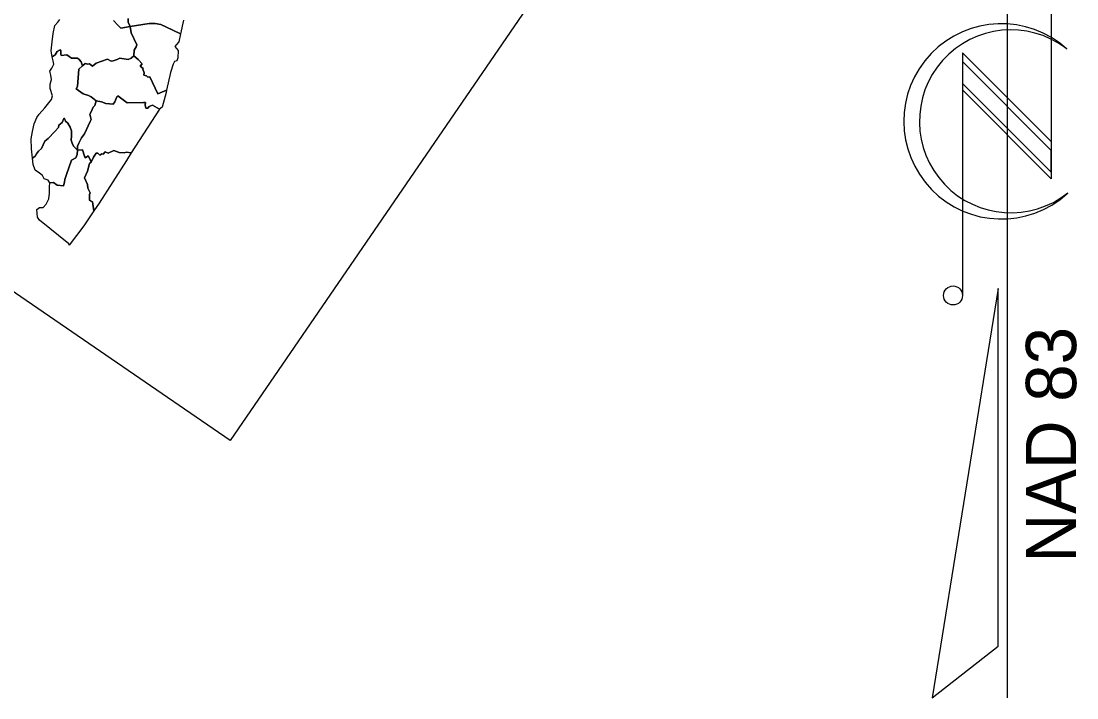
# Model space of a CAD drawing. Extents: x 1638787 to 1643250, y 391480 to 396306.
# Drawn here: x 1641235.6 to 1641581.8, y 395313.5 to 395535.3 of the extents above; entities that cross this region are included whole.
import ezdxf

# ---------------------------------------------------------------- set-up
doc = ezdxf.new("R2010")
doc.units = 0
doc.layers.add('Old_Level_5', color=7, linetype='Continuous')
doc.layers.add('Sheet North Arrow CELL', color=7, linetype='Continuous')

msp = doc.modelspace()

# ---------------------------------------------------------------- linework, layer by layer
at = {"layer": 'Old_Level_5'}
msp.add_lwpolyline([(1641120.36, 395523.82), (1641374.86, 395894.94), (1641558.57, 395768.96), (1641304.08, 395397.83)], close=True, dxfattribs=at)
for points in [[(1641265.88, 395535.48), (1641267.23, 395534), (1641268.21, 395533.04), (1641271.28, 395533.59), (1641271.64, 395531.49), (1641273.51, 395527.54), (1641273.33, 395526.86), (1641272.59, 395525.75), (1641272.47, 395523.92), (1641271.66, 395523.13), (1641270.68, 395522.75), (1641267.92, 395523.18), (1641267.05, 395522.76), (1641265.77, 395522.24), (1641265.05, 395522.2), (1641263.91, 395522.88), (1641260.14, 395521.52), (1641258.92, 395520.5), (1641257.99, 395521.32), (1641257.46, 395521.19), (1641256.57, 395521.4), (1641255.68, 395520.68), (1641255.25, 395521.98), (1641254.63, 395522.69), (1641254.04, 395523.15), (1641252.08, 395523.19), (1641250.53, 395524.23), (1641248.72, 395524.07), (1641248.59, 395524.6), (1641248.6, 395525.61), (1641248.41, 395525.87), (1641247.36, 395525.35), (1641246.76, 395524.29), (1641245.73, 395523.6), (1641245.36, 395525.52), (1641245.69, 395528.53), (1641246.08, 395531.23), (1641246.6, 395533.82), (1641247.65, 395534.99), (1641248.27, 395535.88)], [(1641270.62, 395536.21), (1641270.71, 395535.02), (1641271.28, 395533.59), (1641268.21, 395533.04), (1641267.23, 395534), (1641265.88, 395535.48)], [(1641288.82, 395535.57), (1641287.8, 395531.09), (1641283.06, 395533.41), (1641281.34, 395534.19), (1641279.48, 395534.52), (1641277.59, 395534.52), (1641271.28, 395533.59), (1641270.71, 395535.02), (1641270.62, 395536.21)], [(1641271.28, 395533.59), (1641277.59, 395534.52), (1641279.48, 395534.52), (1641281.34, 395534.19), (1641283.06, 395533.41), (1641287.8, 395531.09), (1641287.26, 395528.55), (1641286.55, 395527.65), (1641285.93, 395526.95), (1641286.48, 395526.37), (1641287.04, 395525.71), (1641286.9, 395523.23), (1641286.68, 395522.32), (1641285.81, 395522.08), (1641285.37, 395521.22), (1641284.5, 395518.47), (1641283.27, 395512.7), (1641280.38, 395511.49), (1641277.8, 395517.06), (1641277.14, 395516.97), (1641276.64, 395517.35), (1641275.84, 395517.64), (1641275.91, 395518.39), (1641275.43, 395519.52), (1641275.54, 395519.83), (1641274.62, 395520.57), (1641275.25, 395521.27), (1641273.89, 395522.74), (1641272.47, 395523.92), (1641272.59, 395525.75), (1641273.33, 395526.86), (1641273.51, 395527.54), (1641271.64, 395531.49), (1641271.28, 395533.59)], [(1641249.56, 395503.38), (1641249.06, 395502.05), (1641247.88, 395501.17), (1641247.79, 395500.41), (1641246.63, 395499.17), (1641244.48, 395496.79), (1641243.38, 395495.91), (1641242.19, 395493.52), (1641241.23, 395492.69), (1641240.58, 395491.75), (1641240.21, 395491.06), (1641239.33, 395490.41), (1641239.01, 395493.44), (1641238.87, 395496.67), (1641239.24, 395499.11), (1641239.86, 395501.59), (1641240.66, 395503.66), (1641241.52, 395504.84), (1641243.34, 395506.92), (1641245.57, 395509.66), (1641245.82, 395510.87), (1641245.12, 395513.27), (1641245.08, 395514.65), (1641245.52, 395516.19), (1641245.27, 395517.6), (1641245.01, 395518.92), (1641245.58, 395519.93), (1641246.26, 395521.19), (1641246.07, 395522.29), (1641245.73, 395523.6), (1641246.76, 395524.29), (1641247.36, 395525.35), (1641248.41, 395525.87), (1641248.6, 395525.61), (1641248.59, 395524.6), (1641248.72, 395524.07), (1641250.53, 395524.23), (1641252.08, 395523.19), (1641254.04, 395523.15), (1641254.63, 395522.69), (1641255.25, 395521.98), (1641255.68, 395520.68), (1641254.53, 395519.58), (1641254.01, 395513.9), (1641253.56, 395513.11), (1641255.87, 395511.49), (1641257.63, 395510.96), (1641258.57, 395510.53), (1641260.19, 395509.18), (1641259.7, 395507.69), (1641259.15, 395507.08), (1641258.54, 395505.53), (1641258.08, 395504.83), (1641258.55, 395503.09), (1641258.15, 395502.35), (1641256.35, 395498.41), (1641255.31, 395497.05), (1641254.54, 395495.31), (1641254.03, 395494.35), (1641254.07, 395492.98), (1641252.81, 395494.17), (1641252.44, 395494.98), (1641252.02, 395496.28), (1641252.06, 395497.74), (1641252.09, 395499.39), (1641251.68, 395500.51), (1641250.89, 395501.87), (1641250.15, 395502.52), (1641249.74, 395503.38), (1641249.56, 395503.38)], [(1641254.53, 395519.58), (1641255.68, 395520.68), (1641256.57, 395521.4), (1641257.46, 395521.19), (1641257.99, 395521.32), (1641258.92, 395520.5), (1641260.14, 395521.52), (1641263.91, 395522.88), (1641265.05, 395522.2), (1641265.77, 395522.24), (1641267.05, 395522.76), (1641267.92, 395523.18), (1641270.68, 395522.75), (1641271.66, 395523.13), (1641272.47, 395523.92), (1641273.89, 395522.74), (1641275.25, 395521.27), (1641274.62, 395520.57), (1641275.54, 395519.83), (1641275.43, 395519.52), (1641275.91, 395518.39), (1641275.84, 395517.64), (1641276.64, 395517.35), (1641277.14, 395516.97), (1641277.8, 395517.06), (1641280.38, 395511.49), (1641283.27, 395512.7), (1641283.17, 395511.94), (1641281.79, 395507.12), (1641280.99, 395506.41), (1641278.64, 395507.76), (1641277.57, 395507.29), (1641277.11, 395506.77), (1641276.49, 395506.81), (1641276.21, 395507.9), (1641276.31, 395508.66), (1641275.64, 395508.66), (1641270.37, 395508.48), (1641267.3, 395510.79), (1641266.92, 395510.45), (1641266.31, 395508.81), (1641265.72, 395508.07), (1641263.33, 395508.34), (1641261.93, 395508.9), (1641260.19, 395509.18), (1641258.57, 395510.53), (1641257.63, 395510.96), (1641255.87, 395511.49), (1641253.56, 395513.11), (1641254.01, 395513.9), (1641254.53, 395519.58)], [(1641286.9, 395523.23), (1641286.68, 395522.32), (1641285.81, 395522.08), (1641285.37, 395521.22), (1641284.5, 395518.47), (1641283.27, 395512.7), (1641283.17, 395511.94)], [(1641259.7, 395507.69), (1641260.19, 395509.18), (1641261.93, 395508.9), (1641263.33, 395508.34), (1641265.72, 395508.07), (1641266.31, 395508.81), (1641266.92, 395510.45), (1641267.3, 395510.79), (1641270.37, 395508.48), (1641275.64, 395508.66), (1641276.31, 395508.66), (1641276.21, 395507.9), (1641276.49, 395506.81), (1641277.11, 395506.77), (1641277.57, 395507.29), (1641278.64, 395507.76), (1641280.99, 395506.41), (1641271.68, 395492.17), (1641269.96, 395492.36), (1641269.49, 395492.1), (1641267.72, 395492.26), (1641265.96, 395492.88), (1641264.07, 395492.03), (1641263.17, 395492.41), (1641262.51, 395491.74), (1641261.98, 395491.79), (1641261.35, 395491.35), (1641260.69, 395492), (1641260.16, 395492.05), (1641259.28, 395490.66), (1641258.57, 395489.02), (1641258.06, 395490.13), (1641257.52, 395491.1), (1641256.98, 395490.67), (1641256.63, 395490.54), (1641256.38, 395491.03), (1641255.64, 395493.1), (1641254.07, 395492.98), (1641254.03, 395494.35), (1641254.54, 395495.31), (1641255.31, 395497.05), (1641256.35, 395498.41), (1641258.15, 395502.35), (1641258.55, 395503.09), (1641258.08, 395504.83), (1641258.54, 395505.53), (1641259.15, 395507.08), (1641259.7, 395507.69)], [(1641254.07, 395492.98), (1641253.98, 395491.55), (1641253.55, 395490.5), (1641252.05, 395489.72), (1641250.41, 395484.99), (1641249.93, 395483.41), (1641249.77, 395482.47), (1641249.49, 395481.29), (1641247.35, 395481.49), (1641246.23, 395482.38), (1641244.96, 395482.33), (1641244.43, 395483.12), (1641243.17, 395483.56), (1641242.56, 395484.66), (1641241.58, 395485.52), (1641240.16, 395486.44), (1641239.55, 395488.29), (1641239.33, 395490.41), (1641240.21, 395491.06), (1641240.58, 395491.75), (1641241.23, 395492.69), (1641242.19, 395493.52), (1641243.38, 395495.91), (1641244.48, 395496.79), (1641246.63, 395499.17), (1641247.79, 395500.41), (1641247.88, 395501.17), (1641249.06, 395502.05), (1641249.56, 395503.38), (1641249.74, 395503.38), (1641250.15, 395502.52), (1641250.89, 395501.87), (1641251.68, 395500.51), (1641252.09, 395499.39), (1641252.06, 395497.74), (1641252.02, 395496.28), (1641252.44, 395494.98), (1641252.81, 395494.17), (1641254.07, 395492.98)], [(1641254.07, 395492.98), (1641255.64, 395493.1), (1641256.38, 395491.03), (1641256.63, 395490.54), (1641256.98, 395490.67), (1641257.52, 395491.1), (1641258.06, 395490.13), (1641258.57, 395489.02), (1641257.99, 395488.62), (1641257.3, 395486.13), (1641256.33, 395483.9), (1641257.29, 395481.8), (1641257.42, 395480.53), (1641258.16, 395479.04), (1641258.03, 395478.49), (1641258, 395476.6), (1641258.29, 395476.44), (1641258.94, 395476.05), (1641259.37, 395473.08), (1641256.08, 395468.15), (1641251.35, 395461.91), (1641251.22, 395462.34), (1641241.6, 395470.1), (1641240.92, 395471.02), (1641240.71, 395473.53), (1641241.64, 395474.22), (1641242.74, 395474.26), (1641243.78, 395475.28), (1641244.63, 395477.02), (1641244.87, 395478.9), (1641244.83, 395480.94), (1641244.96, 395482.33), (1641246.23, 395482.38), (1641247.35, 395481.49), (1641249.49, 395481.29), (1641249.77, 395482.47), (1641249.93, 395483.41), (1641250.41, 395484.99), (1641252.05, 395489.72), (1641253.55, 395490.5), (1641253.98, 395491.55), (1641254.07, 395492.98)], [(1641260.16, 395492.05), (1641260.69, 395492), (1641261.35, 395491.35), (1641261.98, 395491.79), (1641262.51, 395491.74), (1641263.17, 395492.41), (1641264.07, 395492.03), (1641265.96, 395492.88), (1641267.72, 395492.26), (1641269.49, 395492.1), (1641269.96, 395492.36), (1641271.68, 395492.17), (1641270.07, 395489.59), (1641261.11, 395475.64), (1641259.37, 395473.08), (1641258.94, 395476.05), (1641258.29, 395476.44), (1641258, 395476.6), (1641258.03, 395478.49), (1641258.16, 395479.04), (1641257.42, 395480.53), (1641257.29, 395481.8), (1641256.33, 395483.9), (1641257.3, 395486.13), (1641257.99, 395488.62), (1641258.57, 395489.02), (1641259.28, 395490.66), (1641260.16, 395492.05)]]:
    msp.add_lwpolyline(points, dxfattribs=at)
at = {"layer": 'Sheet North Arrow CELL'}
for p, q in [((1641559.01, 395313.46), (1641559.01, 395694.35)), ((1641573.37, 395561.82), (1641573.37, 395483.63)), ((1641573.37, 395495.82), (1641544.27, 395524.96)), ((1641544.27, 395524.96), (1641544.27, 395445.5)), ((1641573.37, 395492.93), (1641544.27, 395522.07)), ((1641544.27, 395522.07), (1641544.27, 395514.91)), ((1641573.37, 395485.81), (1641544.27, 395514.91)), ((1641544.27, 395514.91), (1641573.37, 395485.81)), ((1641573.37, 395483.63), (1641544.27, 395512.77)), ((1641573.37, 395485.81), (1641573.37, 395492.93))]:
    msp.add_line(p, q, dxfattribs=at)
for points in [[(1641578.16, 395526.44), (1641578.53, 395526.16)], [(1641544.27, 395522.07), (1641544.27, 395514.91), (1641573.37, 395485.81), (1641573.37, 395492.93), (1641544.27, 395522.07)], [(1641578.63, 395478.81), (1641578.87, 395479.03)]]:
    msp.add_lwpolyline(points, dxfattribs=at)
msp.add_lwpolyline([(1641555.94, 395447.63), (1641534.37, 395313.46), (1641555.94, 395330.45)], close=True, dxfattribs=at)
msp.add_circle((1641541.18, 395445.37), 3.11, dxfattribs=at)
for centre, radius, start, end in [((1641557.05, 395502.44), 32, 47.84, 312.3941), ((1641557.05, 395502.44), 32, 47.84, 312.3941), ((1641560.15, 395502.46), 29.99, 53.095, 308.6287), ((1641560.15, 395502.46), 29.99, 53.095, 308.6287)]:
    msp.add_arc(centre, radius, start, end, dxfattribs=at)

# ---------------------------------------------------------------- texts
msp.add_text('NAD 83', height=16.5, rotation=90, dxfattribs=at).set_placement((1641581.56, 395357.81))

doc.saveas('drawing.dxf')
